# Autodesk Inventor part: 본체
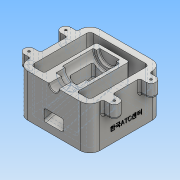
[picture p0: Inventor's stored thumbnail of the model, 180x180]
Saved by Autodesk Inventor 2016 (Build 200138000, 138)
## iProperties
Created: 2018-01
Part Number: 본체
Material: 알루미늄 6061
Document SubType Name: Modeling
Designer: Administrator
Density: 2.7 g/cm^3
Appearance: 알루미늄 - 평지
Mass: 994.806 g
Surface Area: 836.638 cm^2
Volume: 368.447 cm^3
Author: Administrator
## Parameters: d2 = 65 mm, d3 = 0, d4 = 27 mm, d6 = 7.5 mm, d8 = 0, d11 = 3.242 mm, d12 = 9 mm, d13 = 4 mm, d14 = 2 mm, d15 = 90 deg, d16 = 11 mm, d17 = 118 deg, d26 = 0, d31 = 15 mm, d32 = 32 mm, d35 = 19 mm, d36 = 14 mm, d37 = 47 mm, d38 = 5 mm, d39 = 90 deg, d41 = 18 mm, d43 = 105 deg, d45 = 5 mm, d47 = 11.061 mm, d48 = 0, d49 = 0, d50 = 5 mm, d51 = 5 mm, d52 = 5 mm, d53 = 5 mm, d54 = 19 mm, d55 = 0, d57 = 105 deg, d60 = 0, d61 = 15 mm, d65 = 55 mm, d66 = 0.5 mm, d67 = 0, d68 = 3 mm, d69 = 3 mm, d70 = 3 mm, d71 = 3 mm, d72 = 3 mm, d73 = 5 mm, d74 = 3 mm, d75 = 1 mm, d76 = 2 mm, d77 = 45 deg, d78 = 3 mm, d79 = 3 mm, d82 = 3 mm, d83 = 1 mm, d84 = 2.5 mm
